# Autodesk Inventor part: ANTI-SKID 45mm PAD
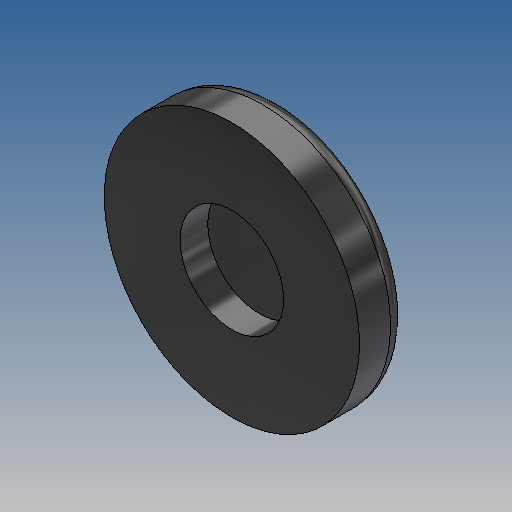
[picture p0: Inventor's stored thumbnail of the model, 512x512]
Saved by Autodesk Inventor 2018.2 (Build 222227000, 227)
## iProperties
Created: 2007-03
Part Number: ANTI-SKID 45mm PAD
Material: Rubber
Document SubType Name: Modeling
Designer: Andy Moles
Mass: 6.20162 g
Surface Area: 30.2508 cm^2
Volume: 6.66841 cm^3
Density: 0.93 g/cm^3
Appearance: Rubber - Black - Version 1.1
Author: Andy Moles
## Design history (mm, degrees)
sketch "Sketch1"
  geometry: C1 r 18.5 at (0, 0); 1 further point
  constraints: 1 centre point, 1 coincident
  dimensions: "d0" = 37 diameter of C1
extrude "Extrusion1" new body sketch "Sketch1" distance "d1" = 7; taper "d2" = 0 deg
sketch "Sketch2"
  geometry: C1 r 18.5 at (0, 0) reference; C2 r 7.5 at (0, 0)
  constraints: 1 centre point, 1 coincident
  dimensions: "d3" = 15 diameter of C2
extrude "Extrusion2" cut sketch "Sketch2" distance "d4" = 4; taper "d5" = 0 deg
fillet "Fillet1" dims "d6" = 2.5
body "Solid1"
